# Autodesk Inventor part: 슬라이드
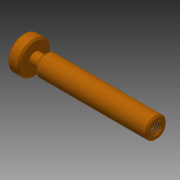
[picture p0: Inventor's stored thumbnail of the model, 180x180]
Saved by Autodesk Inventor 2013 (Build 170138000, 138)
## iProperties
Created: 2015-12
Part Number: 슬라이드
Document SubType Name: Modeling
Designer: mdu
Density: 8.08 g/cm^3
Material: 스테인리스강
Mass: 116.651 g
Surface Area: 50.7862 cm^2
Volume: 14.437 cm^3
Author: mdu
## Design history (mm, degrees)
sketch "스케치1"
  geometry: L1 (-45, 0)-(45, 0); L2 (-45, 0)-(-45, 11); L3 (-45, 11)-(-37, 11); L4 (-37, 11)-(-37, 4); L5 (-37, 4)-(-32, 4); L6 (-32, 4)-(-29, 7); L7 (-29, 7)-(45, 7); L8 (45, 7)-(45, 0); 2 further points
  constraints: 16 end point, 4 parallel, 2 perpendicular, 1 coincident, 1 horizontal, 1 midpoint
  dimensions: "d0" = 90 distance of L1.start L1.end; "d1" = 22 diameter of L3 L1; "d2" = 14 diameter of L7 L1; "d3" = 8 diameter of L5 L1; "d4" = 8 distance of L2.end L3.end; "d5" = 5 distance of L4.end L5.end; "d6" = 135 deg angle of L6 L5
revolve "회전1" sketch "스케치1" stored, may be unused: angle "d7" = 90 deg
chamfer "모따기1" distance "d8" = 1; stored, may be unused: second distance "d9" = 2, angle "d10" = 45 deg
hole "구멍1" diameter "d13" = 6.647; stored, may be unused: countersink angle "d17" = 90 deg, drill point angle "d19" = 118 deg; dims "d11" = 10, "d12" = 10, "d14" = 9, "d15" = 4, "d16" = 2, "d18" = 12
chamfer "모따기2" distance "d20" = 1; stored, may be unused: second distance "d21" = 2, angle "d22" = 45 deg
node "솔리드1"
